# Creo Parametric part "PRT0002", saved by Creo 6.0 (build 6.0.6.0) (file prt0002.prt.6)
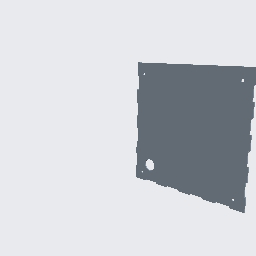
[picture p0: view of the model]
Units: Inch lbm Second (Pro/E Default); INCH, POUND, SECS

Created from: INLBS_PART_SOLID.PRT

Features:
  1. datum plane "RIGHT"
  2. datum plane "TOP"
  3. datum plane "FRONT"
  4. coordinate system
  5. sketch "Sketch 1"
  6. extrusion "Extrude 1"
  7. sketch "Sketch 2"
  8. extruded cut "Extrude 2"
  9. sketch "Sketch 3"
  10. extruded cut "Extrude 3"

Surfaces: 54 plane, 5 cylinder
